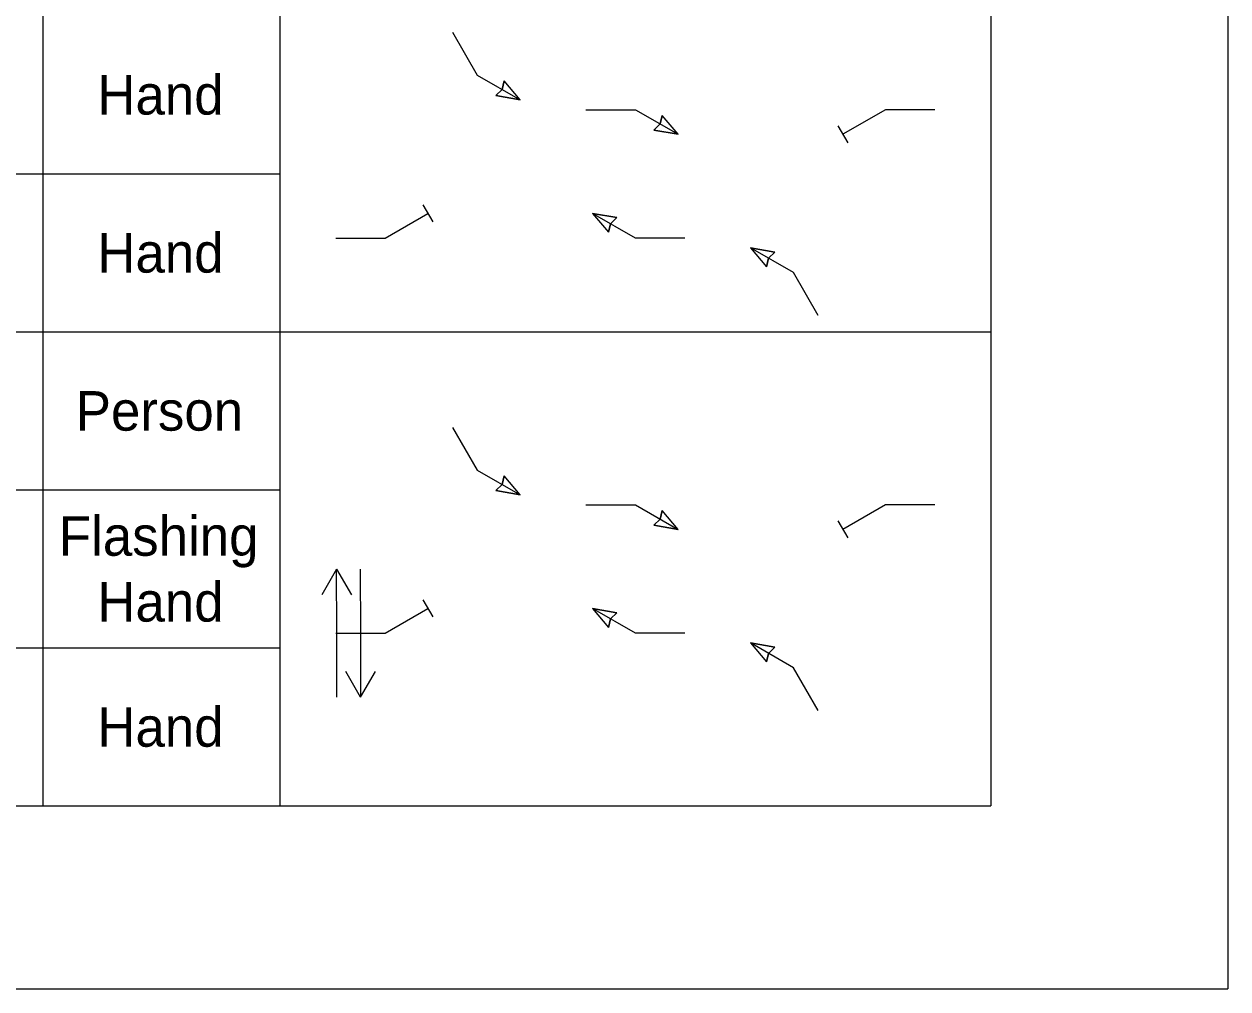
# Model space of a CAD drawing. Extents: x 515543 to 517243, y 660510 to 662861.
# Drawn here: x 516446.4 to 516636.9, y 661900 to 662052.7 of the extents above; entities that cross this region are included whole.
import ezdxf

# ---------------------------------------------------------------- set-up
doc = ezdxf.new("R2010")
doc.units = 0
doc.layers.add('Default', color=7, linetype='Continuous')

msp = doc.modelspace()

# ---------------------------------------------------------------- linework, layer by layer
at = {"layer": 'Default'}
for p, q in [((516636.87, 662735.88), (516636.87, 661900.05)), ((516449.37, 662204), (516449.37, 661929)), ((516486.87, 662204), (516486.87, 661929)), ((516599.37, 662204), (516599.37, 661929)), ((516514.21, 662051.39), (516518.12, 662044.62)), ((516518.12, 662044.62), (516524.88, 662040.71)), ((516522.04, 662042.35), (516522.37, 662043.71)), ((516524.88, 662040.71), (516522.37, 662043.71)), ((516521.04, 662041.39), (516522.04, 662042.35)), ((516524.88, 662040.71), (516521.04, 662041.39)), ((516535.31, 662039.15), (516543.12, 662039.15)), ((516543.12, 662039.15), (516549.88, 662035.25)), ((516582.7, 662039.15), (516575.93, 662035.25)), ((516590.51, 662039.15), (516582.7, 662039.15)), ((516547.04, 662036.89), (516547.37, 662038.24)), ((516549.88, 662035.25), (516547.37, 662038.24)), ((516546.04, 662035.92), (516547.04, 662036.89)), ((516549.88, 662035.25), (516546.04, 662035.92)), ((516575.15, 662036.6), (516576.71, 662033.89)), ((516299.37, 662029), (516486.87, 662029)), ((516509.52, 662024.1), (516511.09, 662021.39)), ((516503.54, 662018.84), (516510.31, 662022.75)), ((516543.12, 662018.84), (516536.35, 662022.75)), ((516536.35, 662022.75), (516540.2, 662022.07)), ((516536.35, 662022.75), (516538.86, 662019.75)), ((516540.2, 662022.07), (516539.19, 662021.11)), ((516539.19, 662021.11), (516538.86, 662019.75)), ((516495.73, 662018.84), (516503.54, 662018.84)), ((516550.93, 662018.84), (516543.12, 662018.84)), ((516568.12, 662013.37), (516561.35, 662017.28)), ((516561.35, 662017.28), (516565.2, 662016.6)), ((516561.35, 662017.28), (516563.86, 662014.28)), ((516565.2, 662016.6), (516564.19, 662015.64)), ((516564.19, 662015.64), (516563.86, 662014.28)), ((516572.02, 662006.6), (516568.12, 662013.37)), ((516224.37, 662004), (516449.37, 662004)), ((516224.37, 662004), (516449.37, 662004)), ((516449.37, 662004), (516599.37, 662004)), ((516449.37, 662004), (516599.37, 662004)), ((516486.87, 662004), (516599.37, 662004)), ((516514.21, 661988.89), (516518.12, 661982.12)), ((516518.12, 661982.12), (516524.88, 661978.21)), ((516521.04, 661978.89), (516522.04, 661979.85)), ((516522.04, 661979.85), (516522.37, 661981.21)), ((516524.88, 661978.21), (516522.37, 661981.21)), ((516299.37, 661979), (516486.87, 661979)), ((516486.87, 661979), (516486.87, 661954)), ((516524.88, 661978.21), (516521.04, 661978.89)), ((516535.31, 661976.65), (516543.12, 661976.65)), ((516543.12, 661976.65), (516549.88, 661972.75)), ((516582.7, 661976.65), (516575.93, 661972.75)), ((516590.51, 661976.65), (516582.7, 661976.65)), ((516546.04, 661973.42), (516547.04, 661974.39)), ((516547.04, 661974.39), (516547.37, 661975.74)), ((516549.88, 661972.75), (516547.37, 661975.74)), ((516575.15, 661974.1), (516576.71, 661971.39)), ((516549.88, 661972.75), (516546.04, 661973.42)), ((516495.86, 661966.46), (516493.52, 661962.4)), ((516495.88, 661956.34), (516495.86, 661966.46)), ((516495.86, 661966.46), (516498.21, 661962.4)), ((516499.61, 661966.46), (516499.63, 661956.34)), ((516509.52, 661961.6), (516511.09, 661958.89)), ((516503.54, 661956.34), (516510.31, 661960.25)), ((516543.12, 661956.34), (516536.35, 661960.25)), ((516536.35, 661960.25), (516540.2, 661959.57)), ((516536.35, 661960.25), (516538.86, 661957.25)), ((516540.2, 661959.57), (516539.19, 661958.61)), ((516539.19, 661958.61), (516538.86, 661957.25)), ((516495.73, 661956.34), (516503.54, 661956.34)), ((516495.9, 661946.22), (516495.88, 661956.34)), ((516499.63, 661956.34), (516499.65, 661946.22)), ((516550.93, 661956.34), (516543.12, 661956.34)), ((516299.37, 661954), (516449.37, 661954)), ((516449.37, 661954), (516486.87, 661954)), ((516568.12, 661950.87), (516561.35, 661954.78)), ((516561.35, 661954.78), (516565.2, 661954.1)), ((516561.35, 661954.78), (516563.86, 661951.78)), ((516564.19, 661953.14), (516563.86, 661951.78)), ((516565.2, 661954.1), (516564.19, 661953.14)), ((516499.65, 661946.22), (516497.3, 661950.28)), ((516499.65, 661946.22), (516502, 661950.28)), ((516572.02, 661944.1), (516568.12, 661950.87)), ((516224.37, 661929), (516599.37, 661929)), ((516186.87, 661900.05), (516636.87, 661900.05))]:
    msp.add_line(p, q, dxfattribs=at)
for points in [[(516521.04, 662041.39), (516524.88, 662040.71), (516522.37, 662043.71), (516522.04, 662042.35), (516521.04, 662041.39), (516521.04, 662041.39)], [(516546.04, 662035.92), (516549.88, 662035.25), (516547.37, 662038.24), (516547.04, 662036.89), (516546.04, 662035.92), (516546.04, 662035.92)], [(516540.2, 662022.07), (516536.35, 662022.75), (516538.86, 662019.75), (516539.19, 662021.11), (516540.2, 662022.07), (516540.2, 662022.07)], [(516565.2, 662016.6), (516561.35, 662017.28), (516563.86, 662014.28), (516564.19, 662015.64), (516565.2, 662016.6), (516565.2, 662016.6)], [(516521.04, 661978.89), (516524.88, 661978.21), (516522.37, 661981.21), (516522.04, 661979.85), (516521.04, 661978.89), (516521.04, 661978.89)], [(516546.04, 661973.42), (516549.88, 661972.75), (516547.37, 661975.74), (516547.04, 661974.39), (516546.04, 661973.42), (516546.04, 661973.42)], [(516540.2, 661959.57), (516536.35, 661960.25), (516538.86, 661957.25), (516539.19, 661958.61), (516540.2, 661959.57), (516540.2, 661959.57)], [(516565.2, 661954.1), (516561.35, 661954.78), (516563.86, 661951.78), (516564.19, 661953.14), (516565.2, 661954.1), (516565.2, 661954.1)]]:
    msp.add_lwpolyline(points, dxfattribs=at)

# ---------------------------------------------------------------- texts
for s, p in [('Hand', (516458, 662038.37)), ('Hand', (516458, 662013.37)), ('Person', (516454.59, 661988.37)), ('Flashing', (516451.91, 661968.58)), ('Hand', (516458, 661958.16)), ('Hand', (516458, 661938.37))]:
    msp.add_text(s, height=6.25, dxfattribs=at).set_placement(p)

doc.saveas('drawing.dxf')
